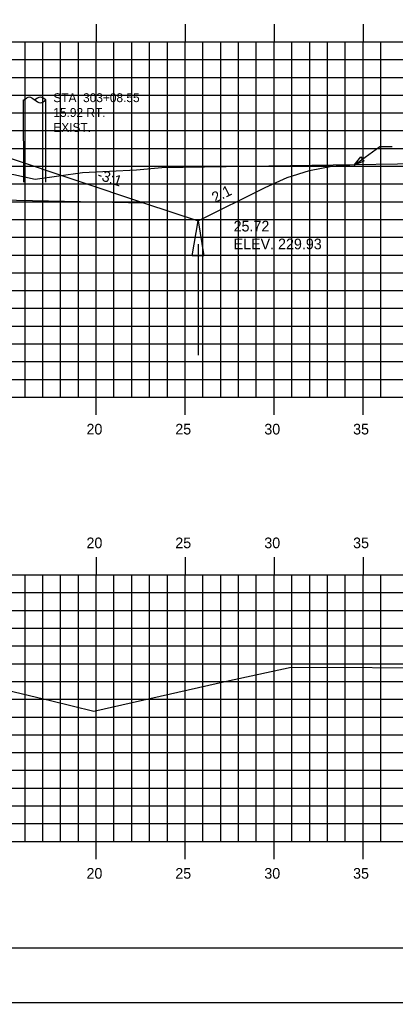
# Model space of a CAD drawing. Extents: x 1136767 to 1136937, y 608981 to 609091.
# Drawn here: x 1136866.1 to 1136887.2, y 608981.3 to 609036.6 of the extents above; entities that cross this region are included whole.
import ezdxf

# ---------------------------------------------------------------- set-up
doc = ezdxf.new("R2010")
doc.units = 0
for name, color, linetype in [('ANNOTATION', 7, 'Continuous'), ('BORDER', 7, 'Continuous'), ('D_Drainage_Ditch_Line', 7, 'Continuous'), ('D_Roadway_SlopeLines', 7, 'Continuous'), ('D_Roadway_SubGrade', 7, 'Continuous'), ('D_Text_Monospaced', 7, 'Continuous'), ('D_Text_Standard', 7, 'Continuous'), ('H_V ANNOTATION', 7, 'Continuous'), ('MAJOR', 7, 'Continuous'), ('MINOR', 7, 'Continuous'), ('PLOT BOUNDARY', 7, 'Continuous'), ('S_Roadway_Centerline', 7, 'Continuous'), ('S_Utilities_Pole_Power', 7, 'Continuous')]:
    doc.layers.add(name, color=color, linetype=linetype)

msp = doc.modelspace()

# ---------------------------------------------------------------- linework, layer by layer
msp.add_lwpolyline([(1136835.382, 609027.955), (1136835.383, 609027.955), (1136839.383, 609028.115), (1136850.383, 609028.555), (1136861.383, 609028.995), (1136865.383, 609028.835), (1136873.107, 609026.26), (1136876.107, 609025.26), (1136879.874, 609027.144), (1136881.124, 609027.694), (1136882.374, 609028.091), (1136883.624, 609028.338), (1136884.874, 609028.433)])
at = {"layer": 'BORDER'}
msp.add_lwpolyline([(1136775.383, 608984.335), (1136935.383, 608984.335), (1136935.383, 609089.335), (1136775.383, 609089.335)], close=True, dxfattribs=at)
at = {"layer": 'D_Drainage_Ditch_Line'}
msp.add_line((1136876.107, 609023.948), (1136876.106, 609017.705), dxfattribs=at)
msp.add_lwpolyline([(1136876.435, 609023.292), (1136875.779, 609023.292), (1136876.107, 609025.26)], close=True, dxfattribs=at)
at = {"layer": 'D_Roadway_SlopeLines'}
for points in [[(1136876.107, 609025.26), (1136879.874, 609027.144), (1136881.124, 609027.694), (1136882.374, 609028.091), (1136883.624, 609028.338), (1136884.874, 609028.433)], [(1136873.107, 609026.26), (1136876.107, 609025.26)]]:
    msp.add_lwpolyline(points, dxfattribs=at)
at = {"layer": 'D_Roadway_SubGrade'}
msp.add_lwpolyline([(1136861.383, 609028.578), (1136861.383, 609028.745), (1136865.383, 609028.585), (1136865.383, 609028.835), (1136865.383, 609028.835), (1136873.107, 609026.26), (1136861.383, 609026.495)], close=True, dxfattribs=at)
at = {"layer": 'D_Text_Standard'}
msp.add_lwpolyline([(1136884.874, 609028.394), (1136886.33, 609029.447), (1136887.01, 609029.447)], dxfattribs=at)
msp.add_lwpolyline([(1136884.874, 609028.394), (1136885.261, 609028.853), (1136885.431, 609028.618)], close=True, dxfattribs=at)
at = {"layer": 'MAJOR'}
for p, q in [((1136870.383, 609036.337), (1136870.383, 609035.335)), ((1136875.383, 609036.337), (1136875.383, 609035.335)), ((1136880.383, 609036.337), (1136880.383, 609035.335)), ((1136885.383, 609036.337), (1136885.383, 609035.335)), ((1136780.383, 609035.335), (1136920.383, 609035.335)), ((1136780.383, 609035.335), (1136920.383, 609035.335)), ((1136870.383, 609015.335), (1136870.383, 609035.335)), ((1136875.383, 609015.335), (1136875.383, 609035.335)), ((1136880.383, 609015.335), (1136880.383, 609035.335)), ((1136885.383, 609015.335), (1136885.383, 609035.335)), ((1136780.383, 609030.335), (1136920.383, 609030.335)), ((1136780.383, 609025.335), (1136920.383, 609025.335)), ((1136780.383, 609020.335), (1136920.383, 609020.335)), ((1136780.383, 609015.335), (1136920.383, 609015.335)), ((1136780.383, 609015.335), (1136920.383, 609015.335)), ((1136870.383, 609014.333), (1136870.383, 609015.335)), ((1136875.383, 609014.333), (1136875.383, 609015.335)), ((1136880.383, 609014.333), (1136880.383, 609015.335)), ((1136885.383, 609014.333), (1136885.383, 609015.335)), ((1136870.383, 609006.337), (1136870.383, 609005.335)), ((1136875.383, 609006.337), (1136875.383, 609005.335)), ((1136880.383, 609006.337), (1136880.383, 609005.335)), ((1136885.383, 609006.337), (1136885.383, 609005.335)), ((1136780.383, 609005.335), (1136920.383, 609005.335)), ((1136780.383, 609005.335), (1136920.383, 609005.335)), ((1136870.383, 608990.335), (1136870.383, 609005.335)), ((1136875.383, 608990.335), (1136875.383, 609005.335)), ((1136880.383, 608990.335), (1136880.383, 609005.335)), ((1136885.383, 608990.335), (1136885.383, 609005.335)), ((1136780.383, 609000.335), (1136920.383, 609000.335)), ((1136780.383, 608995.335), (1136920.383, 608995.335)), ((1136780.383, 608990.335), (1136920.383, 608990.335)), ((1136780.383, 608990.335), (1136920.383, 608990.335)), ((1136870.383, 608989.333), (1136870.383, 608990.335)), ((1136875.383, 608989.333), (1136875.383, 608990.335)), ((1136880.383, 608989.333), (1136880.383, 608990.335)), ((1136885.383, 608989.333), (1136885.383, 608990.335))]:
    msp.add_line(p, q, dxfattribs=at)
at = {"layer": 'MINOR'}
for p, q in [((1136866.383, 609015.335), (1136866.383, 609035.335)), ((1136867.383, 609015.335), (1136867.383, 609035.335)), ((1136868.383, 609015.335), (1136868.383, 609035.335)), ((1136869.383, 609015.335), (1136869.383, 609035.335)), ((1136871.383, 609015.335), (1136871.383, 609035.335)), ((1136872.383, 609015.335), (1136872.383, 609035.335)), ((1136873.383, 609015.335), (1136873.383, 609035.335)), ((1136874.383, 609015.335), (1136874.383, 609035.335)), ((1136876.383, 609015.335), (1136876.383, 609035.335)), ((1136877.383, 609015.335), (1136877.383, 609035.335)), ((1136878.383, 609015.335), (1136878.383, 609035.335)), ((1136879.383, 609015.335), (1136879.383, 609035.335)), ((1136881.383, 609015.335), (1136881.383, 609035.335)), ((1136882.383, 609015.335), (1136882.383, 609035.335)), ((1136883.383, 609015.335), (1136883.383, 609035.335)), ((1136884.383, 609015.335), (1136884.383, 609035.335)), ((1136886.383, 609015.335), (1136886.383, 609035.335)), ((1136780.383, 609034.335), (1136920.383, 609034.335)), ((1136780.383, 609033.335), (1136920.383, 609033.335)), ((1136780.383, 609032.335), (1136920.383, 609032.335)), ((1136780.383, 609031.335), (1136920.383, 609031.335)), ((1136780.383, 609029.335), (1136920.383, 609029.335)), ((1136780.383, 609028.335), (1136920.383, 609028.335)), ((1136780.383, 609027.335), (1136920.383, 609027.335)), ((1136780.383, 609026.335), (1136920.383, 609026.335)), ((1136780.383, 609024.335), (1136920.383, 609024.335)), ((1136780.383, 609023.335), (1136920.383, 609023.335)), ((1136780.383, 609022.335), (1136920.383, 609022.335)), ((1136780.383, 609021.335), (1136920.383, 609021.335)), ((1136780.383, 609019.335), (1136920.383, 609019.335)), ((1136780.383, 609018.335), (1136920.383, 609018.335)), ((1136780.383, 609017.335), (1136920.383, 609017.335)), ((1136780.383, 609016.335), (1136920.383, 609016.335)), ((1136866.383, 608990.335), (1136866.383, 609005.335)), ((1136867.383, 608990.335), (1136867.383, 609005.335)), ((1136868.383, 608990.335), (1136868.383, 609005.335)), ((1136869.383, 608990.335), (1136869.383, 609005.335)), ((1136871.383, 608990.335), (1136871.383, 609005.335)), ((1136872.383, 608990.335), (1136872.383, 609005.335)), ((1136873.383, 608990.335), (1136873.383, 609005.335)), ((1136874.383, 608990.335), (1136874.383, 609005.335)), ((1136876.383, 608990.335), (1136876.383, 609005.335)), ((1136877.383, 608990.335), (1136877.383, 609005.335)), ((1136878.383, 608990.335), (1136878.383, 609005.335)), ((1136879.383, 608990.335), (1136879.383, 609005.335)), ((1136881.383, 608990.335), (1136881.383, 609005.335)), ((1136882.383, 608990.335), (1136882.383, 609005.335)), ((1136883.383, 608990.335), (1136883.383, 609005.335)), ((1136884.383, 608990.335), (1136884.383, 609005.335)), ((1136886.383, 608990.335), (1136886.383, 609005.335)), ((1136780.383, 609004.335), (1136920.383, 609004.335)), ((1136780.383, 609003.335), (1136920.383, 609003.335)), ((1136780.383, 609002.335), (1136920.383, 609002.335)), ((1136780.383, 609001.335), (1136920.383, 609001.335)), ((1136780.383, 608999.335), (1136920.383, 608999.335)), ((1136780.383, 608998.335), (1136920.383, 608998.335)), ((1136780.383, 608997.335), (1136920.383, 608997.335)), ((1136780.383, 608996.335), (1136920.383, 608996.335)), ((1136780.383, 608994.335), (1136920.383, 608994.335)), ((1136780.383, 608993.335), (1136920.383, 608993.335)), ((1136780.383, 608992.335), (1136920.383, 608992.335)), ((1136780.383, 608991.335), (1136920.383, 608991.335))]:
    msp.add_line(p, q, dxfattribs=at)
at = {"layer": 'PLOT BOUNDARY'}
msp.add_lwpolyline([(1136767.29, 608981.276), (1136937.29, 608981.276), (1136937.29, 609091.276), (1136767.29, 609091.276)], close=True, dxfattribs=at)
at = {"layer": 'S_Roadway_Centerline'}
for points in [[(1136822.194, 609027.792), (1136827.669, 609027.966), (1136833.537, 609028.081), (1136837.169, 609028.144), (1136838.739, 609028.139), (1136843.157, 609028.309), (1136849.946, 609028.538), (1136859.641, 609028.552), (1136860.485, 609028.559), (1136863.029, 609028.225), (1136865.76, 609027.861), (1136866.958, 609027.606), (1136869.62, 609027.988), (1136872.643, 609028.131), (1136874.07, 609028.265), (1136888.517, 609028.49), (1136889.712, 609028.507), (1136889.937, 609028.505), (1136905.048, 609028.329), (1136909.628, 609028.345), (1136920.383, 609028.314)], [(1136819.07, 608999.229), (1136827.733, 608999.346), (1136831.155, 608999.469), (1136836.465, 608999.354), (1136837.328, 608999.415), (1136838.592, 608999.439), (1136839.398, 608999.507), (1136844.656, 608999.671), (1136850.774, 608999.819), (1136856.604, 608999.836), (1136861.347, 608999.808), (1136867.818, 608998.265), (1136870.243, 608997.662), (1136877.713, 608999.351), (1136881.339, 609000.131), (1136890.461, 609000.106), (1136896.884, 609000.009), (1136898.771, 608999.999), (1136909.82, 609000.138), (1136917.953, 609000.183), (1136919.115, 609000.153), (1136920.383, 609000.132)]]:
    msp.add_lwpolyline(points, dxfattribs=at)
at = {"layer": 'S_Utilities_Pole_Power'}
for p, q in [((1136866.307, 609027.442), (1136866.303, 609032.061)), ((1136866.307, 609032.061), (1136866.463, 609032.172)), ((1136866.775, 609032.172), (1136866.931, 609032.061)), ((1136867.088, 609032.172), (1136866.931, 609032.061)), ((1136866.931, 609032.061), (1136867.088, 609031.95)), ((1136867.557, 609032.061), (1136867.401, 609032.172)), ((1136867.401, 609031.95), (1136867.557, 609032.061)), ((1136867.557, 609027.442), (1136867.553, 609032.061))]:
    msp.add_line(p, q, dxfattribs=at)
for centre, start, end in [((1136866.619, 609031.951), 90, 125.2644), ((1136866.619, 609031.951), 54.7356, 90), ((1136867.244, 609031.951), 90, 125.2644), ((1136867.244, 609032.172), 234.7356, 270), ((1136867.244, 609031.951), 54.7356, 90), ((1136867.244, 609032.172), 270, 305.2644)]:
    msp.add_arc(centre, 0.271, start, end, dxfattribs=at)

# ---------------------------------------------------------------- texts
at = {"layer": 'ANNOTATION'}
for s, rotation, p in [('-3:1', 341.5652, (1136870.395, 609027.619)), ('2:1', 26.5651, (1136877.063, 609026.257))]:
    msp.add_text(s, height=0.6, rotation=rotation, dxfattribs=at).set_placement(p)
at = {"layer": 'D_Text_Monospaced'}
for s, height, p in [('STA. 303+08.55', 0.49998, (1136867.973, 609031.94)), ('15.92 RT.', 0.5, (1136867.973, 609031.106)), ('EXIST. ', 0.5, (1136867.973, 609030.266))]:
    msp.add_text(s, height=height, dxfattribs=at).set_placement(p)
at = {"layer": 'D_Text_Standard'}
for s, p in [('25.72', (1136878.107, 609024.66)), ('ELEV. 229.93', (1136878.107, 609023.658))]:
    msp.add_text(s, height=0.6, dxfattribs=at).set_placement(p)
at = {"layer": 'H_V ANNOTATION'}
for s, p in [('20', (1136869.837, 609013.235)), ('25', (1136874.829, 609013.235)), ('30', (1136879.832, 609013.235)), ('35', (1136884.824, 609013.235)), ('20', (1136869.837, 609006.835)), ('25', (1136874.829, 609006.835)), ('30', (1136879.832, 609006.835)), ('35', (1136884.824, 609006.835)), ('20', (1136869.837, 608988.235)), ('25', (1136874.829, 608988.235)), ('30', (1136879.832, 608988.235)), ('35', (1136884.824, 608988.235))]:
    msp.add_text(s, height=0.6, dxfattribs=at).set_placement(p)

doc.saveas('drawing.dxf')
